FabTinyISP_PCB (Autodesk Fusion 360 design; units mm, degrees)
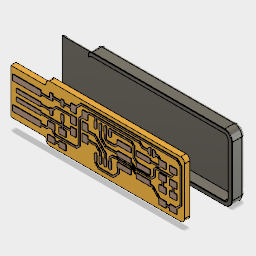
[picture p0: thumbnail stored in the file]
canvas "Canvas1"
sketch "Sketch1"
  line L1 (-22.3791, 2.7847) -> (-22.3791, 4.2731)
  line L2 (-14.896, 2.7847) -> (-22.3791, 2.7847)
  line L3 (-14.896, 3.3177) -> (-14.896, 2.7847)
  line L4 (-11.7521, 3.3177) -> (-14.896, 3.3177)
  line L5 (-11.7521, 4.0569) -> (-11.7521, 3.3177)
  line L6 (-9.59, 4.0569) -> (-11.7521, 4.0569)
  line L7 (-9.59, 3.3666) -> (-9.59, 4.0569)
  line L8 (-8.8001, 3.3666) -> (-9.59, 3.3666)
  line L9 (-8.8001, 4.0569) -> (-8.8001, 3.3666)
  line L10 (-7.045, 4.0569) -> (-8.8001, 4.0569)
  line L11 (-7.045, 3.4448) -> (-7.045, 4.0569)
  line L12 (-5.5486, 3.4448) -> (-7.045, 3.4448)
  line L13 (-5.5486, 4.8474) -> (-5.5486, 3.4448)
  line L14 (-4.1837, 6.2102) -> (-5.5486, 4.8474)
  line L15 (21.0265, 6.2102) -> (-4.1837, 6.2102)
  line L16 (21.9226, 5.3085) -> (21.0265, 6.2102)
  line L17 (21.9226, -3.5686) -> (21.9226, 5.3085)
  line L18 (20.7842, -4.712) -> (21.9226, -3.5686)
  line L19 (19.1308, -4.712) -> (20.7842, -4.712)
  line L20 (19.1308, -5.2438) -> (19.1308, -4.712)
  line L21 (18.2191, -5.2438) -> (19.1308, -5.2438)
  line L22 (18.2191, -4.712) -> (18.2191, -5.2438)
  line L23 (16.6025, -4.712) -> (18.2191, -4.712)
  line L24 (14.6845, -2.8023) -> (16.6025, -4.712)
  line L25 (14.0279, -2.8023) -> (14.6845, -2.8023)
  line L26 (14.0279, -1.9949) -> (14.0279, -2.8023)
  line L27 (10.3542, -1.9949) -> (14.0279, -1.9949)
  line L28 (10.3542, -2.0964) -> (10.3542, -1.9949)
  line L29 (10.0808, -2.0964) -> (10.3542, -2.0964)
  line L30 (9.1614, -1.181) -> (10.0808, -2.0964)
  line L31 (5.1396, -1.181) -> (9.1614, -1.181)
  line L32 (5.0127, -1.1414) -> (5.1396, -1.181)
  line L33 (3.9455, -1.1414) -> (5.0127, -1.1414)
  line L34 (3.1902, -1.8881) -> (3.9455, -1.1414)
  line L35 (3.1902, -2.8326) -> (3.1902, -1.8881)
  line L36 (-4.3339, 6.6032) -> (-5.6157, 5.3234)
  line L37 (21.1822, 6.6032) -> (-4.3339, 6.6032)
  line L38 (22.31, 5.4684) -> (21.1822, 6.6032)
  line L39 (22.31, -3.7212) -> (22.31, 5.4684)
  line L40 (21.0409, -4.9958) -> (22.31, -3.7212)
  line L41 (14.5149, -3.2066) -> (16.3349, -5.0187)
  line L42 (9.0634, -1.5079) -> (9.9584, -2.399)
  line L43 (5.0429, -1.5079) -> (9.0634, -1.5079)
  line L44 (4.1151, -1.559) -> (4.9791, -1.559)
  line L45 (3.5912, -2.077) -> (4.1151, -1.559)
  line L46 (3.5912, -2.8326) -> (3.5912, -2.077)
  line L47 (9.9584, -2.399) -> (10.3542, -2.399)
  line L48 (10.3542, -3.2624) -> (10.3542, -2.399)
  line L49 (14.0275, -3.2624) -> (10.3542, -3.2624)
  line L50 (14.0275, -3.2066) -> (14.0275, -3.2624)
  line L51 (14.5149, -3.2066) -> (14.0275, -3.2066)
  line L52 (16.3349, -6.21) -> (16.3349, -5.0187)
  line L53 (18.225, -6.21) -> (16.3349, -6.21)
  line L54 (18.225, -5.6595) -> (18.225, -6.21)
  line L55 (19.1308, -5.6595) -> (18.225, -5.6595)
  line L56 (19.1308, -6.21) -> (19.1308, -5.6595)
  line L57 (21.0409, -6.21) -> (19.1308, -6.21)
  line L58 (21.0409, -4.9958) -> (21.0409, -6.21)
  line L59 (-7.045, 5.3234) -> (-5.6157, 5.3234)
  line L60 (-7.045, 4.4624) -> (-7.045, 5.3234)
  line L61 (-8.8001, 4.9647) -> (-8.8001, 4.4624)
  line L62 (-9.59, 4.9647) -> (-8.8001, 4.9647)
  line L63 (-9.59, 4.4624) -> (-9.59, 4.9647)
  line L64 (-11.7521, 4.4624) -> (-9.59, 4.4624)
  line L65 (-11.7521, 4.9647) -> (-11.7521, 4.4624)
  line L66 (-12.5367, 4.9647) -> (-11.7521, 4.9647)
  line L67 (-12.5367, 3.7233) -> (-12.5367, 4.9647)
  line L68 (-14.896, 3.7233) -> (-12.5367, 3.7233)
  line L69 (-14.896, 4.2788) -> (-14.896, 3.7233)
  line L70 (-22.3791, 4.2731) -> (-14.896, 4.2788)
  line L71 (-8.8001, 4.4624) -> (-7.045, 4.4624)
  line L72 (-14.896, 1.2124) -> (-14.896, 1.5183)
  line L73 (-12.5313, 1.2124) -> (-14.896, 1.2124)
  line L74 (-12.5313, 1.5654) -> (-12.5313, 1.2124)
  line L75 (-11.9293, 1.5654) -> (-12.5313, 1.5654)
  line L76 (-10.8753, 2.6004) -> (-11.9293, 1.5654)
  line L77 (-7.045, 2.6004) -> (-10.8753, 2.6004)
  line L78 (-7.045, 2.6627) -> (-7.045, 2.6004)
  line L79 (-5.5486, 2.6627) -> (-7.045, 2.6627)
  line L80 (-5.5486, 0.7444) -> (-5.5486, 2.6627)
  line L81 (-7.045, 0.7444) -> (-5.5486, 0.7444)
  line L82 (-7.045, 2.2151) -> (-7.045, 0.7444)
  line L83 (-10.6887, 2.2151) -> (-7.045, 2.2151)
  line L84 (-11.746, 1.1767) -> (-10.6887, 2.2151)
  line L85 (-11.746, -0.04) -> (-11.746, 1.1767)
  line L86 (-12.5313, -0.04) -> (-11.746, -0.04)
  line L87 (-12.5313, 0.792) -> (-12.5313, -0.04)
  line L88 (-14.896, 0.792) -> (-12.5313, 0.792)
  line L89 (-14.896, 0.5183) -> (-14.896, 0.792)
  line L90 (-21.3795, 0.5183) -> (-14.896, 0.5183)
  line L91 (-21.3795, 1.5183) -> (-21.3795, 0.5183)
  line L92 (-14.896, 1.5183) -> (-21.3795, 1.5183)
  line L93 (5.0429, -1.5079) -> (4.9791, -1.559)
  line L94 (3.7413, -4.4393) -> (3.7407, -3.1193)
  line L95 (3.0413, -4.4396) -> (3.0407, -3.1196)
  line L96 (-21.3795, -1.4843) -> (-21.3795, -0.4843)
  line L97 (-14.896, -1.4843) -> (-21.3795, -1.4843)
  line L98 (-14.896, -1.1885) -> (-14.896, -1.4843)
  line L99 (-9.4227, -1.1885) -> (-14.896, -1.1885)
  line L100 (-9.4227, -1.7137) -> (-9.4227, -1.1885)
  line L101 (-10.1493, -1.7137) -> (-9.4227, -1.7137)
  line L102 (-10.1493, -3.245) -> (-10.1493, -1.7137)
  line L103 (-8.2571, -3.245) -> (-10.1493, -3.245)
  line L104 (-8.2571, -1.7137) -> (-8.2571, -3.245)
  line L105 (-9.0009, -1.7137) -> (-8.2571, -1.7137)
  line L106 (-9.0009, -1.1885) -> (-9.0009, -1.7137)
  line L107 (-7.049, -1.1885) -> (-9.0009, -1.1885)
  line L108 (-7.049, -1.9154) -> (-7.049, -1.1885)
  line L109 (-5.5486, -1.9154) -> (-7.049, -1.9154)
  line L110 (-5.5486, -0.0299) -> (-5.5486, -1.9154)
  line L111 (-7.049, -0.0299) -> (-5.5486, -0.0299)
  line L112 (-7.049, -0.7686) -> (-7.049, -0.0299)
  line L113 (-9.0009, -0.7686) -> (-7.049, -0.7686)
  line L114 (-9.0009, -0.0355) -> (-9.0009, -0.7686)
  line L115 (-8.7975, -0.0355) -> (-9.0009, -0.0355)
  line L116 (-8.7975, 1.567) -> (-8.7975, -0.0355)
  line L117 (-9.5912, 1.567) -> (-8.7975, 1.567)
  line L118 (-9.5912, -0.0355) -> (-9.5912, 1.567)
  line L119 (-9.4227, -0.0355) -> (-9.5912, -0.0355)
  line L120 (-9.4227, -0.7686) -> (-9.4227, -0.0355)
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  point P443 (-29.6645, 0)
  point P444 (-30.4889, 0)
  dimension "d19" distance P443 P444 = 0.8244
canvas "Canvas2"
sketch "Sketch2"
  line L1 (24.0636, 8.449) -> (-24.0636, 8.449)
  line L2 (24.0636, -8.449) -> (24.0636, 8.449)
  line L3 (-24.0636, -8.449) -> (24.0636, -8.449)
  line L4 (-24.0636, 8.449) -> (-24.0636, -8.449)
extrude "Extrude4" new body sketch "Sketch2" blind -1.4
extrude "Extrude5" new body sketch "Sketch1" blind 0.15
extrude "Extrude7" cut sketch "Sketch1" blind -1.4
extrude "Extrude8" new body sketch "Sketch1" blind 1.6
move "Move1"
sketch "Sketch3" plane through (0, 0, 13.6) normal (0, 0, 1) x axis (1, 0, 0)
  line L1 (-22.9713, -5.9097) -> (-14.0831, -5.9097)
  line L2 (-22.9713, 5.9097) -> (-22.9713, -5.9097)
  line L3 (-14.0831, 5.9097) -> (-22.9713, 5.9097)
  line L4 (21.9589, 7.4133) -> (-12.7135, 7.4133)
  line L5 (22.9687, -6.2879) -> (22.9687, 6.2879)
  line L6 (-12.7135, -7.4133) -> (21.9589, -7.4133)
  line L7 (24.0636, 8.449) -> (24.0636, -8.449)
  line L8 (-24.0636, 8.449) -> (24.0636, 8.449)
  line L9 (-24.0636, -8.449) -> (-24.0636, 8.449)
  line L10 (24.0636, -8.449) -> (-24.0636, -8.449)
  line L11 (-13.6326, -8.449) -> (-13.6326, 8.449)
  line L12 (-13.6326, 8.449) -> (24.0636, 8.449)
  line L13 (-13.6326, -8.449) -> (-13.6326, 8.449)
  line L14 (24.0636, -8.449) -> (-13.6326, -8.449)
  line L15 (24.0636, 8.449) -> (24.0636, -8.449)
  arc A1 centre (-12.6749, -6.4543) radius 0.9598 clockwise from (-12.7135, -7.4133) to (-13.6326, -6.3909)
  arc A2 centre (-14.0831, -6.3611) radius 0.4514 clockwise from (-14.0831, -5.9097) to (-13.6326, -6.3909)
  arc A3 centre (-14.0831, 6.3611) radius 0.4514 clockwise from (-13.6326, 6.3909) to (-14.0831, 5.9097)
  arc A4 centre (-12.6749, 6.4543) radius 0.9598 clockwise from (-13.6326, 6.3909) to (-12.7135, 7.4133)
  arc A5 centre (21.9589, 6.3976) radius 1.0157 clockwise from (21.9589, 7.4133) to (22.9687, 6.2879)
  arc A6 centre (21.9589, -6.3976) radius 1.0157 clockwise from (22.9687, -6.2879) to (21.9589, -7.4133)
extrude "Extrude11" add sketch "Sketch3" profile of A1 A2 L1 L2 L3 A3 A4 L4 A5 L5 A6 L6 L7 L8 L10 L11 L12 L13 L14 L15 along normal blind 1
extrude "Extrude12" cut sketch "Sketch3" profile of A1 A2 L1 L2 L3 A3 A4 L8 L9 L10 L11 L13 against normal blind 1.6
fillet "Fillet1" radius 2
fillet "Fillet2" radius 1
fillet "Fillet3" radius 0.1
fillet "Fillet4" radius 0.1
delete_face "DeleteFace1"
delete_face "DeleteFace2"
fillet "Fillet5" radius 0.1
fillet "Fillet6" radius 0.1
fillet "Fillet7" radius 1
offset_faces "OffsetFaces1" distance 1
scale "Scale2" ScaleX 1.01 ScaleY 1.04
component_from_bodies "Body->Comp"
move "Move21" RotateAngle -180
extrude "Extrude10" new body sketch "Sketch3" profile of A1 A2 L1 L2 L3 A3 A4 L4 A5 L5 A6 L6 L7 L8 L10 L11 L12 L13 L14 L15 along normal blind 1
extrude "Extrude9" cut sketch "Sketch3" profile of A1 A2 L1 L2 L3 A3 A4 L8 L9 L10 L11 against normal blind 1.6
extrude "Extrude1" new body sketch "Sketch2" blind -1.5
extrude "Extrude2" cut sketch "Sketch1" blind -0.5
extrude "Extrude3" cut sketch "Sketch1" blind -1
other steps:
base_feature "Base Feature"
create_component "CreateComponent1"
remove_body "RemoveBody1"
